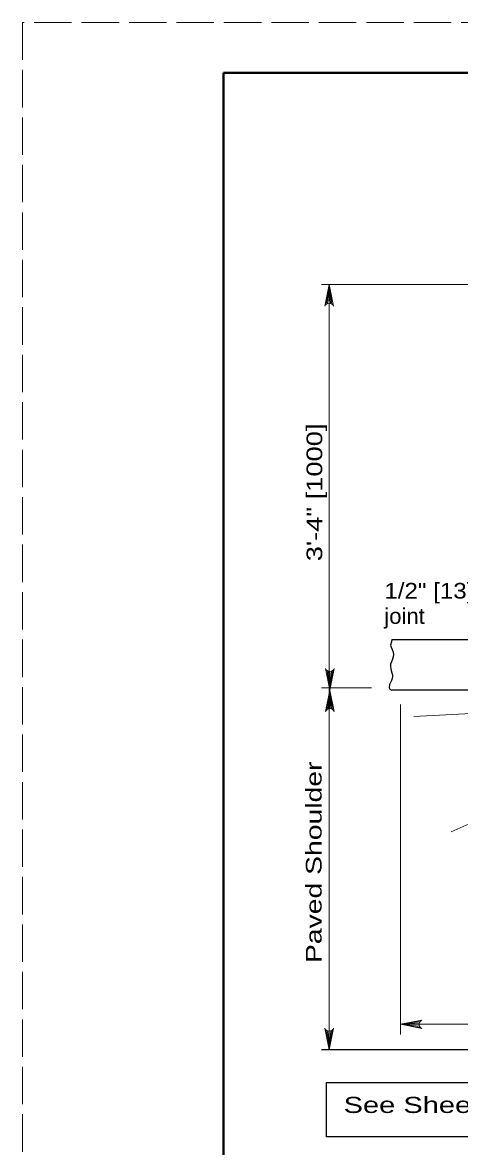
# Model space of a CAD drawing. Extents: x 758.3 to 792.3, y 849.7 to 893.7.
# Drawn here: x 758.32 to 762.67, y 882.51 to 893.69 of the extents above; entities that cross this region are included whole.
import ezdxf

# ---------------------------------------------------------------- set-up
doc = ezdxf.new("R2010")
doc.units = 0
doc.header["$LTSCALE"] = 0.062
doc.linetypes.add('LONG_DASHED', pattern=[7.5, 6, -1.5])
doc.layers.add('1', color=7, linetype='Continuous', lineweight=13)

msp = doc.modelspace()

# ---------------------------------------------------------------- linework, layer by layer
at = {"layer": '1', "lineweight": 25}
for p, q in [((760.3205, 893.18817), (791.8205, 893.18817)), ((761.99533, 887.55475), (764.85108, 887.55475)), ((767.821, 883.47342), (761.29283, 883.47342))]:
    msp.add_line(p, q, dxfattribs=at)
at = {"layer": '1'}
for p, q in [((761.29283, 891.08192), (764.788, 891.08192)), ((761.3415, 890.88575), (761.3715, 891.08192)), ((761.354, 890.89317), (761.3715, 891.08192)), ((761.3715, 890.89658), (761.3715, 891.08192)), ((761.38517, 890.89458), (761.3715, 891.08192)), ((761.39858, 890.888), (761.3715, 891.08192)), ((761.3715, 883.47342), (761.3715, 891.08192)), ((761.35, 887.24483), (761.37708, 887.05092)), ((761.36342, 887.23825), (761.37708, 887.05092)), ((761.40708, 887.24708), (761.37708, 887.05092)), ((761.3945, 887.23967), (761.37708, 887.05092)), ((761.37708, 887.23625), (761.37708, 887.05092)), ((761.79183, 887.07317), (761.29283, 887.07317)), ((761.34708, 886.85475), (761.37708, 887.05092)), ((761.35967, 886.86217), (761.37708, 887.05092)), ((761.37708, 886.86558), (761.37708, 887.05092)), ((761.39083, 886.86358), (761.37708, 887.05092)), ((761.40425, 886.857), (761.37708, 887.05092)), ((762.0795, 883.62567), (762.0795, 886.906)), ((765.42125, 886.94958), (762.2115, 886.78842)), ((763.002, 885.82942), (762.58433, 885.64092)), ((762.27333, 883.75392), (762.0795, 883.72683)), ((762.26675, 883.7405), (762.0795, 883.72683)), ((764.05883, 883.72683), (762.0795, 883.72683)), ((762.26483, 883.72683), (762.0795, 883.72683)), ((762.26825, 883.70942), (762.0795, 883.72683)), ((762.27567, 883.69683), (762.0795, 883.72683)), ((761.34433, 883.66725), (761.3715, 883.47342)), ((761.35775, 883.66067), (761.3715, 883.47342)), ((761.40142, 883.66958), (761.3715, 883.47342)), ((761.38892, 883.66217), (761.3715, 883.47342)), ((761.3715, 883.65867), (761.3715, 883.47342))]:
    msp.add_line(p, q, dxfattribs=at)
at = {"layer": '1', "linetype": 'LONG_DASHED'}
msp.add_lwpolyline([(758.3205, 871.68817), (792.3205, 871.68817), (792.3205, 893.68817), (758.3205, 893.68817)], close=True, dxfattribs=at)
at = {"layer": '1', "lineweight": 25}
for points in [[(791.8205, 872.18817), (760.3205, 872.18817), (760.3205, 893.18817)], [(761.99533, 887.55475), (761.98925, 887.529), (761.98008, 887.49842), (761.98725, 887.47708), (761.99842, 887.45467), (762.00858, 887.42717), (762.01067, 887.40383), (762.00758, 887.38242), (761.99942, 887.35808), (761.98925, 887.33258), (761.98108, 887.30917), (761.98108, 887.28683), (761.98425, 887.26042), (761.98725, 887.24508), (761.99542, 887.22075), (761.99942, 887.20233), (762.00142, 887.18408), (761.99842, 887.16475), (761.99025, 887.14642), (761.98008, 887.12608), (761.97092, 887.10475), (761.96792, 887.07317), (761.97508, 887.05792), (761.99533, 887.05092)], [(779.047, 887.05092), (775.87267, 887.05092), (761.99533, 887.05092)]]:
    msp.add_lwpolyline(points, dxfattribs=at)
at = {"layer": '1', "lineweight": 40}
msp.add_lwpolyline([(760.3205, 893.18817), (791.8205, 893.18817), (791.8205, 872.18817), (760.3205, 872.18817)], close=True, dxfattribs=at)
at = {"layer": '1'}
for points in [[(761.32867, 890.86775), (761.3715, 891.08192), (761.41433, 890.86775)], [(761.41992, 887.26508), (761.37708, 887.05092), (761.33425, 887.26508)], [(761.33425, 886.83675), (761.37708, 887.05092), (761.41992, 886.83675)], [(762.29367, 883.684), (762.0795, 883.72683), (762.29367, 883.76967)], [(761.41433, 883.68758), (761.3715, 883.47342), (761.32867, 883.68758)]]:
    msp.add_lwpolyline(points, dxfattribs=at)
at = {"layer": '1', "lineweight": 25}
msp.add_lwpolyline([(761.3445, 883.14692), (765.98558, 883.14692), (765.98558, 882.60908), (761.3445, 882.60908)], close=True, dxfattribs=at)
at = {"layer": '1'}
for centre, start, end in [((761.37151, 890.85045), 22.08782, 157.91395), ((761.37706, 887.28237), 202.08782, 337.91395), ((761.37715, 886.81943), 22.08782, 157.91395), ((762.31093, 883.72688), 112.08782, 247.91395), ((761.37142, 883.70485), 202.08782, 337.91395)]:
    msp.add_arc(centre, 0.04623, start, end, dxfattribs=at)

# ---------------------------------------------------------------- texts
for s, width, p in [('3\'-4" [1000]', 1.3, (761.30183, 888.33108)), ('Paved Shoulder', 1.35, (761.29517, 884.336))]:
    msp.add_text(s, height=0.156, rotation=90, dxfattribs=dict(at, width=width)).set_placement(p)
for s, height, width, p in [('1/2" [13] exp.', 0.156, 1.15, (761.9195, 887.95983)), ('joint', 0.156, 1.05, (761.9195, 887.70867)), ('See Sheet 2 of 2 for Sections', 0.16, 1.35, (761.51425, 882.84542))]:
    msp.add_text(s, height=height, dxfattribs=dict(at, width=width)).set_placement(p)

doc.saveas('drawing.dxf')
